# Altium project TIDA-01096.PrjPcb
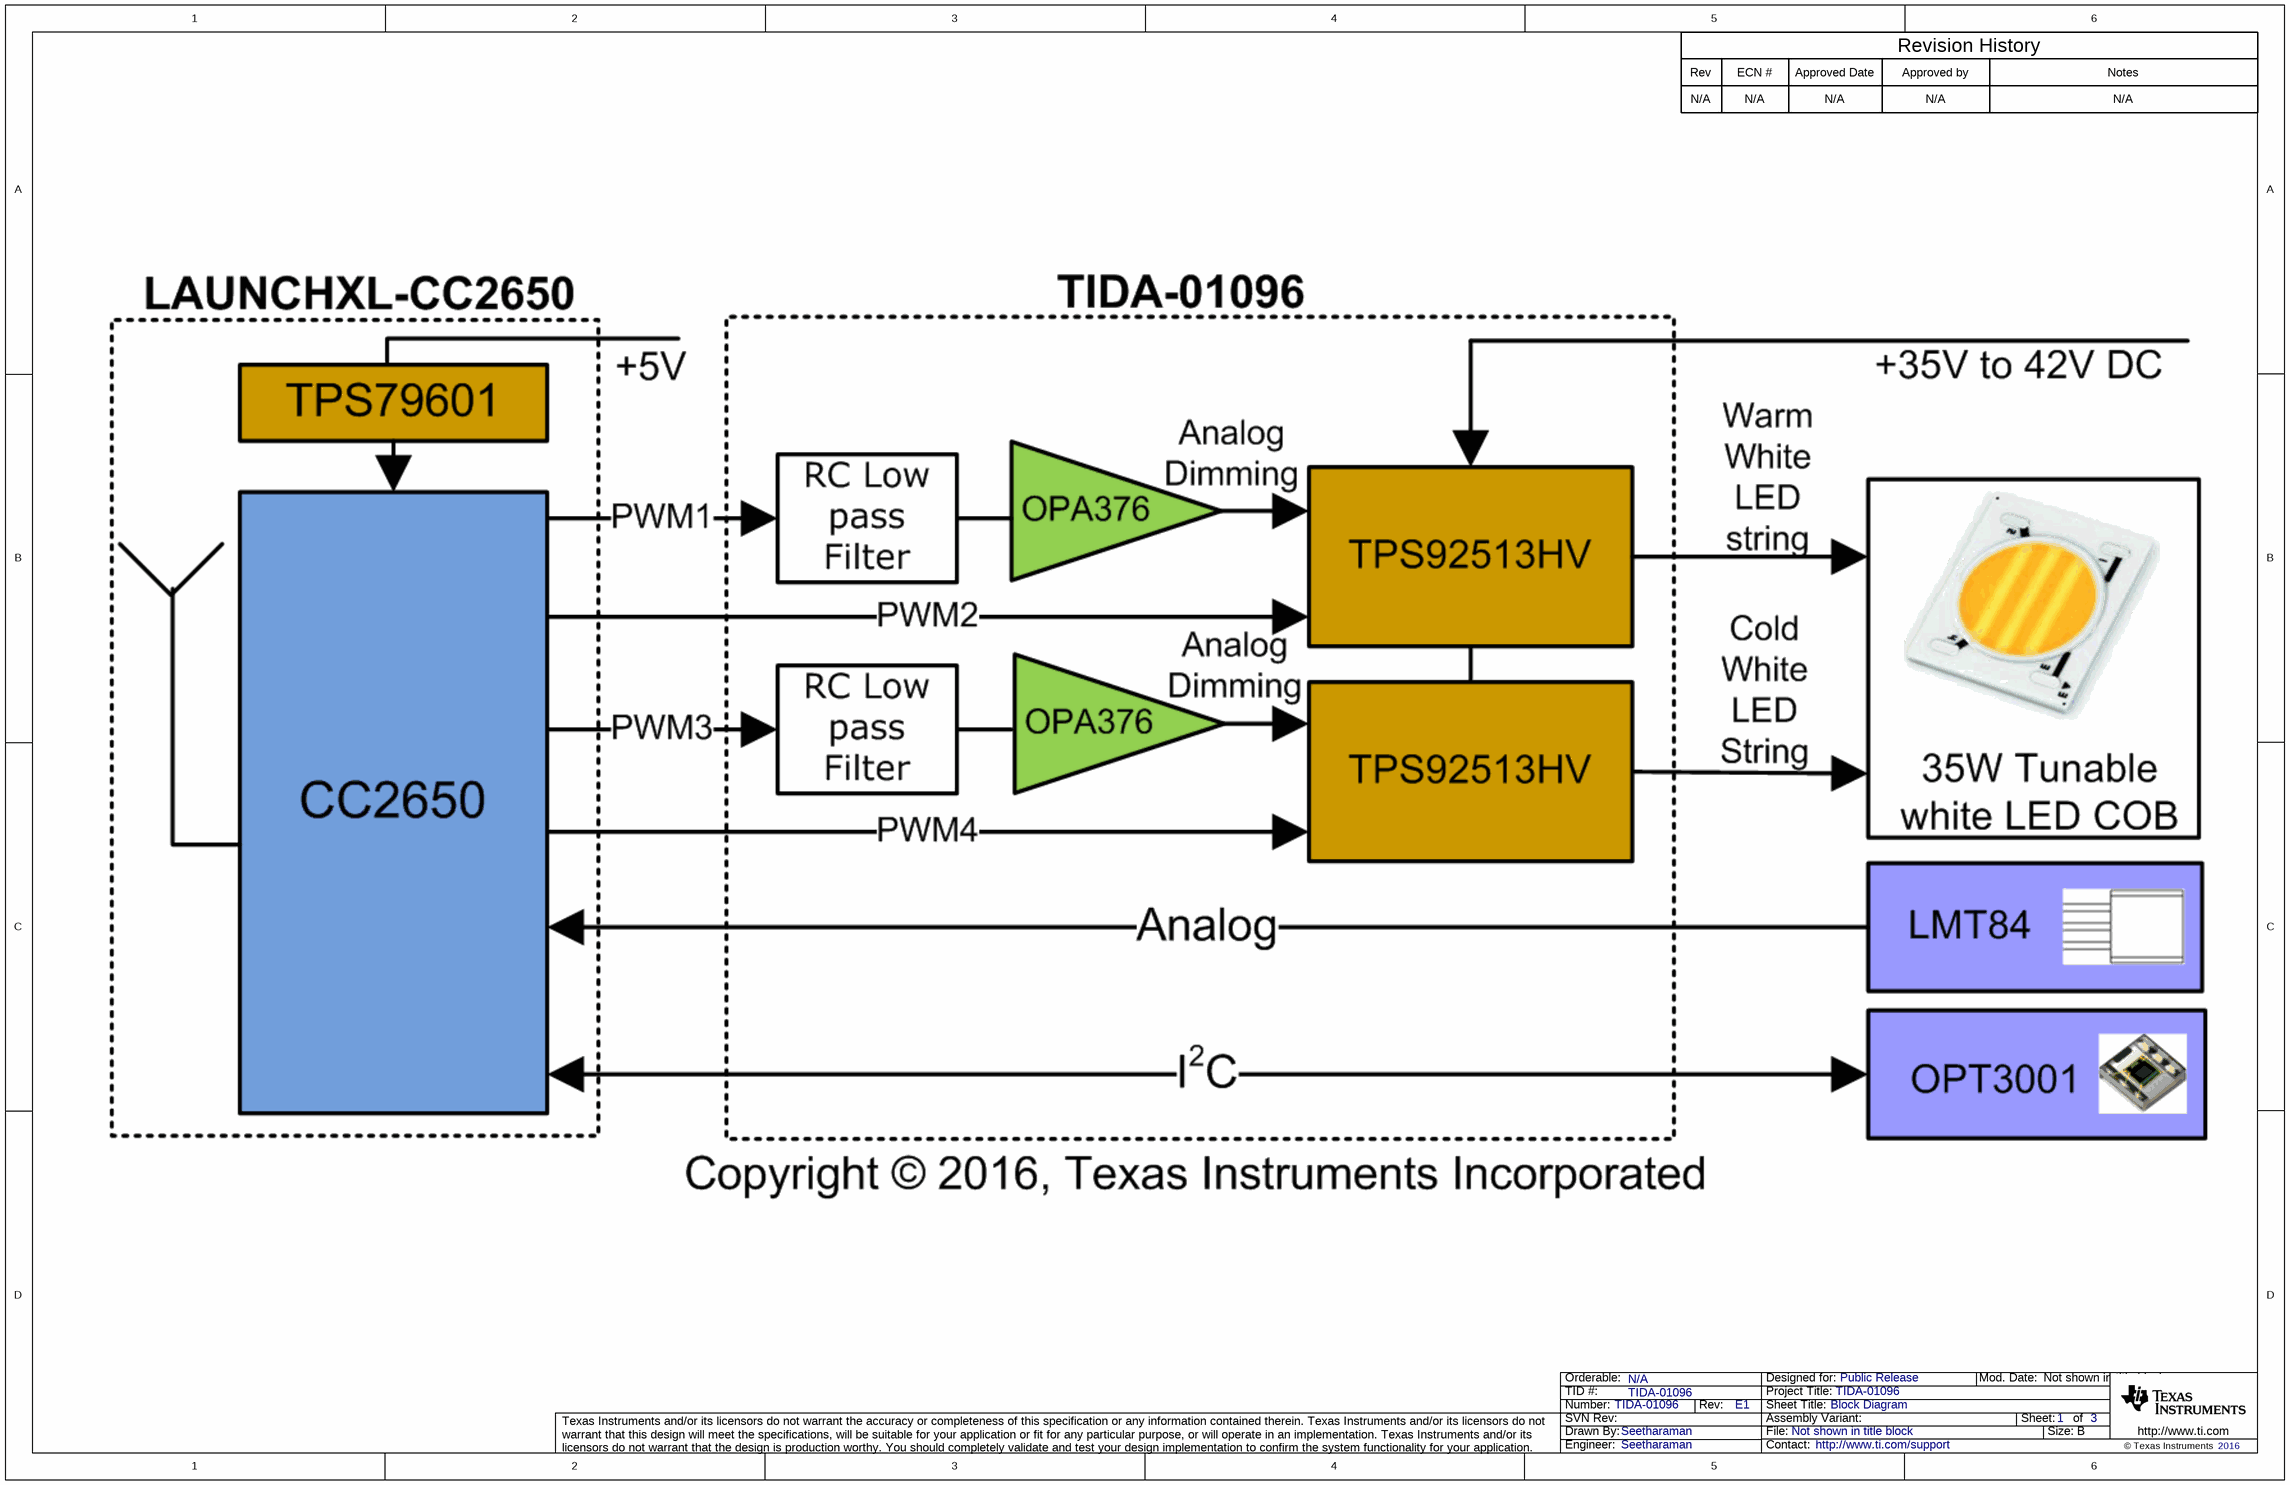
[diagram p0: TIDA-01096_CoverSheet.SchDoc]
CopyrightYear: 2016; EVM_Orderable: N/A; PCB_Layout: Avinash; PCB_Rev: E1; PRJ_Customer: Public Release; PRJ_Engineer: Seetharaman; PRJ_Number: TIDA-01096; PRJ_Title: TIDA-01096; SCH_Rev: E1; TechSupport: http://www.ti.com/support; TID: TIDA-01096
3 sheets, 118 parts. Net scope: global (net labels, ports and power ports of the same name join across sheets).
Board file: TIDA-01096.PcbDoc
Sheets:
  TIDA-01096_CoverSheet.SchDoc
  TIDA-01096_Sheet1.SchDoc
  TIDA-01096_Hardware.SchDoc

## Sheet TIDA-01096_CoverSheet.SchDoc: Block Diagram
size 431 x 279 mm; Date: Not shown in title block; ApprovedBy: Not shown in title block; CheckedBy: Not shown in title block; Author: Not shown in title block; CompanyName: Not shown in title block; DrawnBy: Seetharaman; Engineer: Not shown in title block; Organization: Not shown in title block; Address1: Not shown in title block; Address2: Not shown in title block; Address3: Not shown in title block; Address4: Not shown in title block; DocumentNumber: 1; Revision: Use project parameter SCH_Rev; SheetNumber: 1; SheetTotal: 3; PageSetup: Record=PageOptions¦CenterHorizontal=True¦CenterVertical=True¦PrintScale=1.00¦XCorrection=1.00¦YCorrection=1.00¦PrintKind=0¦BorderSize=5000000¦LeftOffset=0¦BottomOffset=0¦Orientation=2¦PaperLength=1000¦PaperWidth=1000¦Scale=100¦PaperSource=15¦PrintQuality=600¦MediaType=1¦DitherType=10¦PaperKind=Letter¦PrintScaleMode=1

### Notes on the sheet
- Rev
- N/A
- ECN #
- Approved Date
- Approved by
- Revision History
- Notes

## Sheet TIDA-01096_Sheet1.SchDoc: TIDA-01096
size 431 x 279 mm; Date: Not shown in title block; ApprovedBy: Not shown in title block; CheckedBy: Not shown in title block; Author: Not shown in title block; CompanyName: Not shown in title block; DrawnBy: Seetharaman; Engineer: Not shown in title block; Organization: Not shown in title block; Address1: Not shown in title block; Address2: Not shown in title block; Address3: Not shown in title block; Address4: Not shown in title block; DocumentNumber: 1; Revision: Use project parameter SCH_Rev; SheetNumber: 2; SheetTotal: 3; PageSetup: Record=PageOptions¦CenterHorizontal=True¦CenterVertical=True¦PrintScale=1.00¦XCorrection=1.00¦YCorrection=1.00¦PrintKind=0¦BorderSize=5000000¦LeftOffset=0¦BottomOffset=0¦Orientation=2¦PaperLength=1000¦PaperWidth=1000¦Scale=100¦PaperSource=15¦PrintQuality=600¦MediaType=1¦DitherType=10¦PaperKind=Letter¦PrintScaleMode=1
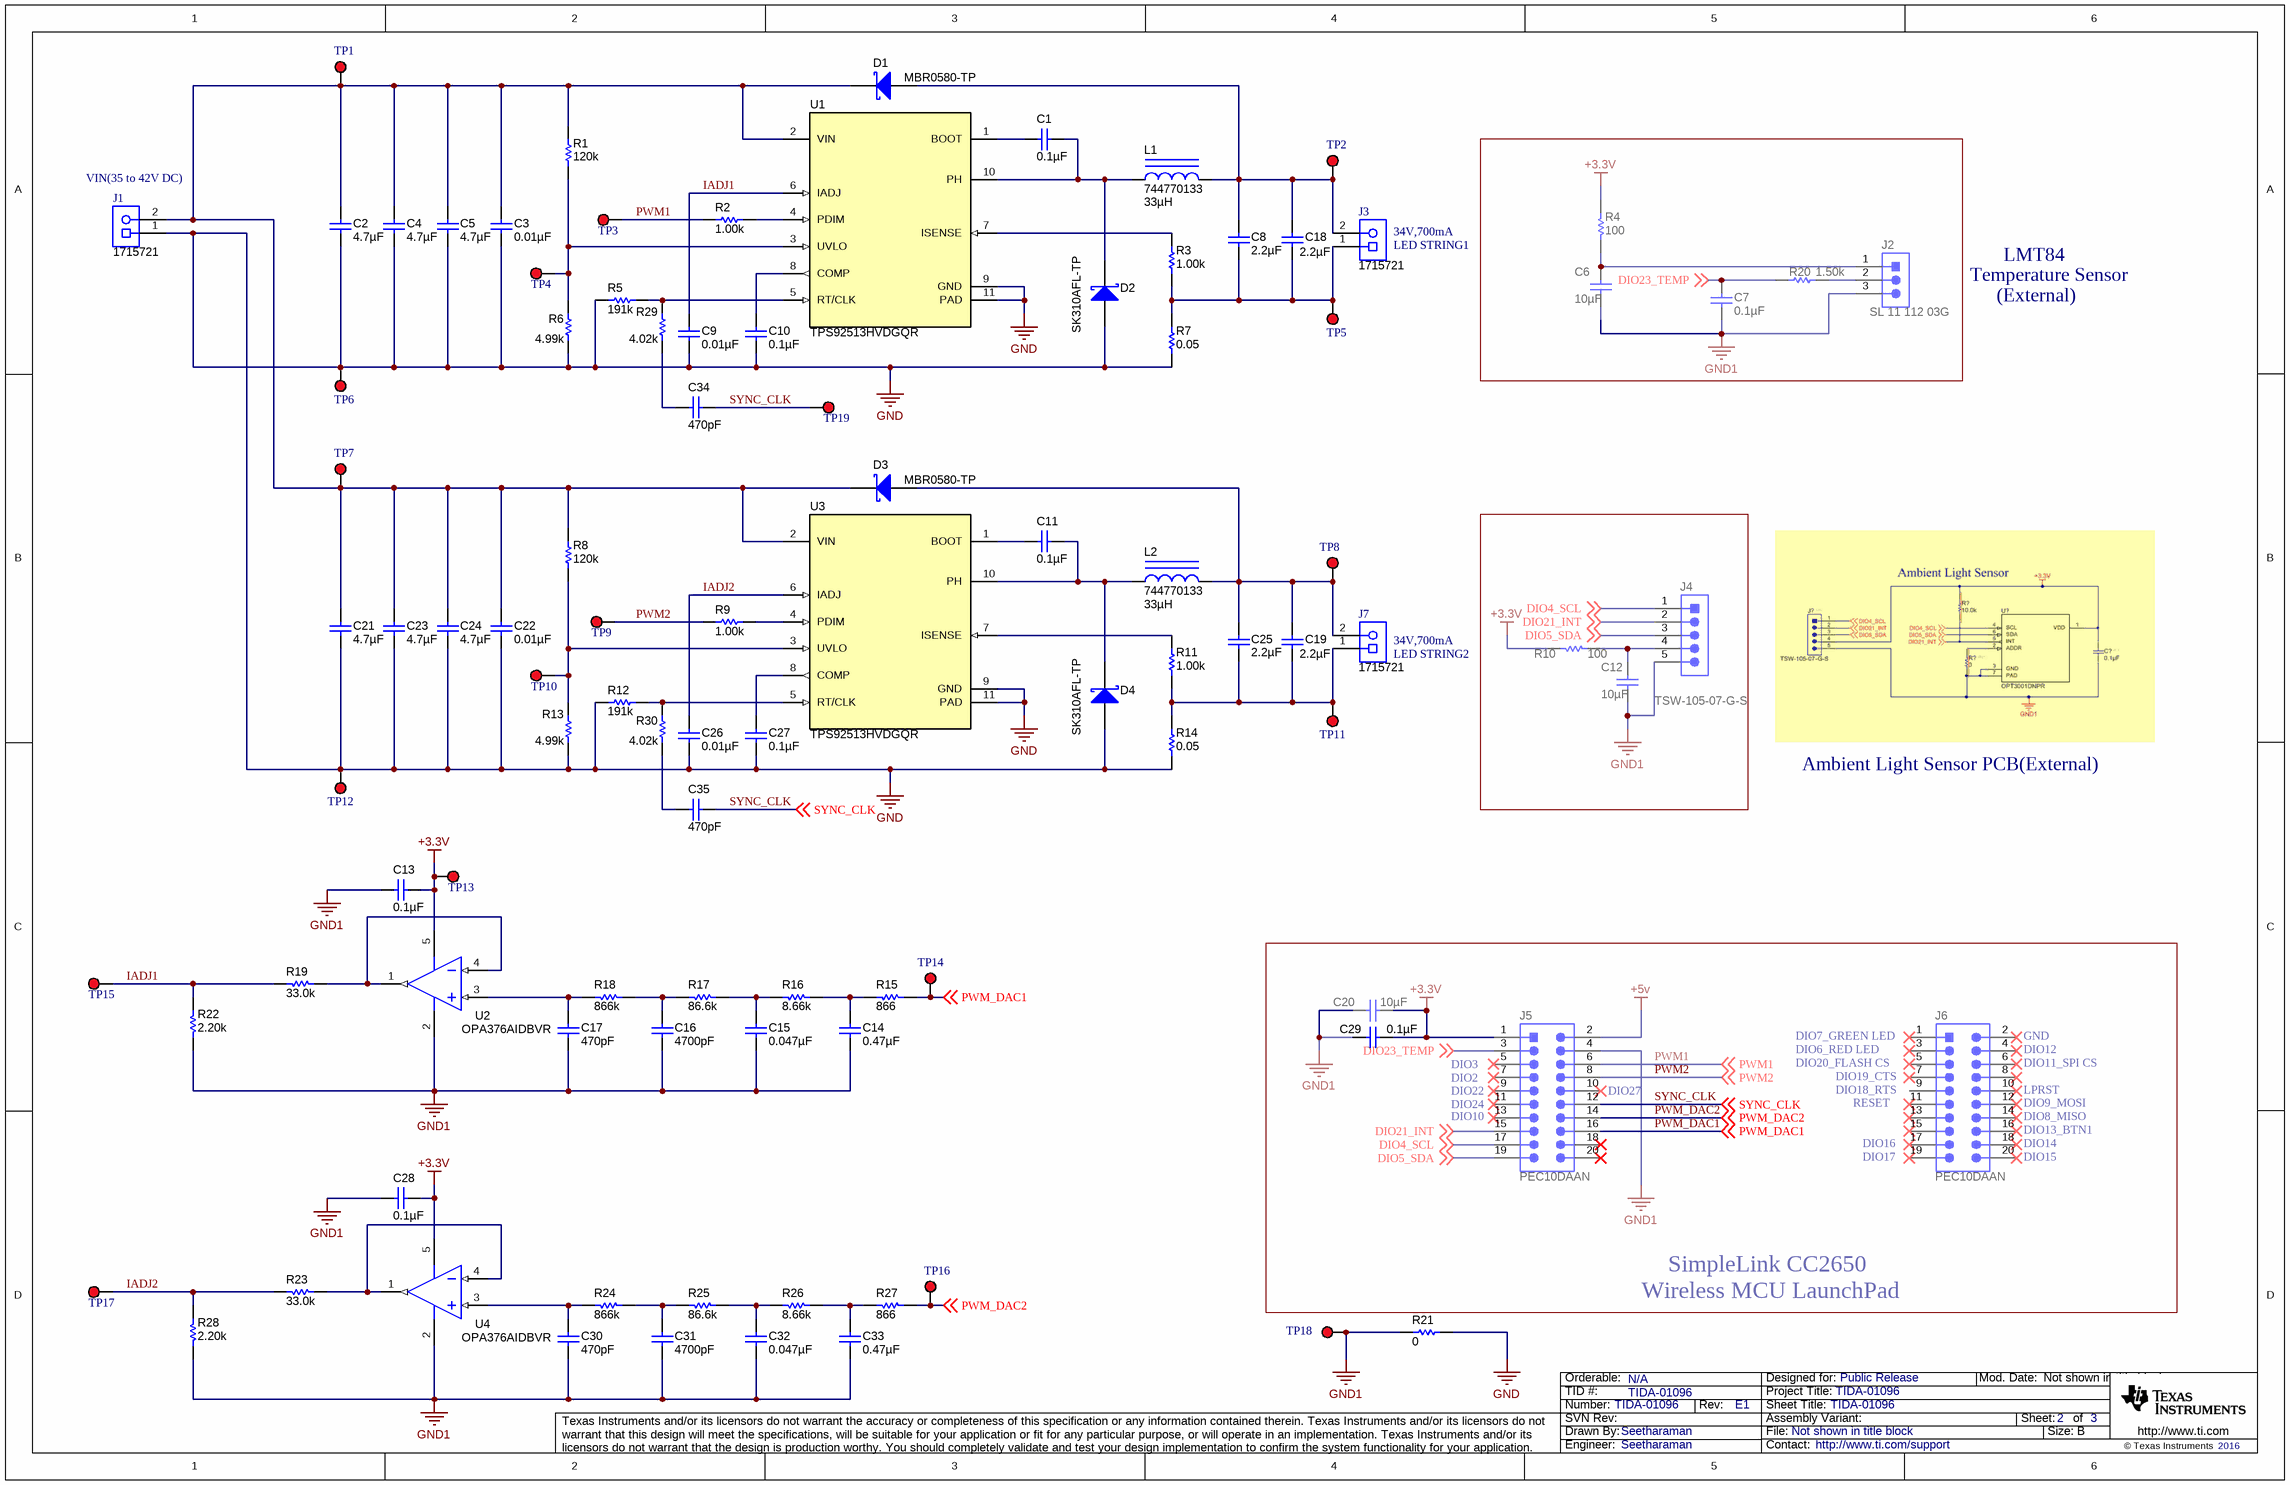
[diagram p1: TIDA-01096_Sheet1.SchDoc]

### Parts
C1  ValueDisplayed: 0.1µF  [0603]  (hidden comment: GRM188R71E104KA01D)
C2  ValueDisplayed: 4.7µF  [1210_220]  (hidden comment: GRJ32DC72A475KE11L)
C3  ValueDisplayed: 0.01µF  [0603]  (hidden comment: GCM188R72A103KA37D)
C4  ValueDisplayed: 4.7µF  [1210_220]  (hidden comment: GRJ32DC72A475KE11L)
C5  ValueDisplayed: 4.7µF  [1210_220]  (hidden comment: GRJ32DC72A475KE11L)
C6  ValueDisplayed: 10µF  [0603]  (hidden comment: GRT188C81A106ME13D)
C7  ValueDisplayed: 0.1µF  [0603]  (hidden comment: GCM188R71H104KA57D)
C8  ValueDisplayed: 2.2µF  [1210_270]  (hidden comment: GRM32ER72A225KA35L)
C9  ValueDisplayed: 0.01µF  [0603]  (hidden comment: GRM188R71E103KA01D)
C10  ValueDisplayed: 0.1µF  [0603]  (hidden comment: GCM188R71H104KA57D)
C11  ValueDisplayed: 0.1µF  [0603]  (hidden comment: GRM188R71E104KA01D)
C12  ValueDisplayed: 10µF  [0603]  (hidden comment: GRT188C81A106ME13D)
C13  ValueDisplayed: 0.1µF  [0603]  (hidden comment: GCM188R71H104KA57D)
C14  ValueDisplayed: 0.47µF  [0603]  (hidden comment: GRM188R71A474KA61D)
C15  ValueDisplayed: 0.047µF  [0402]  (hidden comment: GRM155R71A473KA01D)
C16  ValueDisplayed: 4700pF  [0603]  (hidden comment: GCM188R72A103KA37D)
C17  ValueDisplayed: 470pF  [0603]  (hidden comment: C0603X471K5RACTU)
C18  ValueDisplayed: 2.2µF  [1210_270]  (hidden comment: GRM32ER72A225KA35L)
C19  ValueDisplayed: 2.2µF  [1210_270]  (hidden comment: GRM32ER72A225KA35L)
C20  ValueDisplayed: 10µF  [0603]  (hidden comment: GRT188C81A106ME13D)
C21  ValueDisplayed: 4.7µF  [1210_220]  (hidden comment: GRJ32DC72A475KE11L)
C22  ValueDisplayed: 0.01µF  [0603]  (hidden comment: GCM188R72A103KA37D)
C23  ValueDisplayed: 4.7µF  [1210_220]  (hidden comment: GRJ32DC72A475KE11L)
C24  ValueDisplayed: 4.7µF  [1210_220]  (hidden comment: GRJ32DC72A475KE11L)
C25  ValueDisplayed: 2.2µF  [1210_270]  (hidden comment: GRM32ER72A225KA35L)
C26  ValueDisplayed: 0.01µF  [0603]  (hidden comment: GRM188R71E103KA01D)
C27  ValueDisplayed: 0.1µF  [0603]  (hidden comment: GCM188R71H104KA57D)
C28  ValueDisplayed: 0.1µF  [0603]  (hidden comment: GCM188R71H104KA57D)
C29  ValueDisplayed: 0.1µF  [0603]  (hidden comment: GRM188R71E104KA01D)
C30  ValueDisplayed: 470pF  [0603]  (hidden comment: C0603X471K5RACTU)
C31  ValueDisplayed: 4700pF  [0603]  (hidden comment: GCM188R72A103KA37D)
C32  ValueDisplayed: 0.047µF  [0402]  (hidden comment: GRM155R71A473KA01D)
C33  ValueDisplayed: 0.47µF  [0603]  (hidden comment: GRM188R71A474KA61D)
C34  ValueDisplayed: 470pF  [0603]  (hidden comment: C0603X471K5RACTU)
C35  ValueDisplayed: 470pF  [0603]  (hidden comment: C0603X471K5RACTU)
D1  MBR0580-TP  [SOD-123]
D2  SK310AFL-TP  [SMA]
D3  MBR0580-TP  [SOD-123]
D4  SK310AFL-TP  [SMA]
J1  1715721  [PhoenixContact_1715721]
J2  SL 11 112 03G  [Fischer_SL-11-112-03G]
J3  1715721  [PhoenixContact_1715721]
J4  TSW-105-07-G-S  [TSW-105-07-G-S]
J5  PEC10DAAN  [SULLINS_PEC10DAAN]
J6  PEC10DAAN  [SULLINS_PEC10DAAN]
J7  1715721  [PhoenixContact_1715721]
L1  744770133  ValueDisplayed: 33µH  [WE-PD-XL]
L2  744770133  ValueDisplayed: 33µH  [WE-PD-XL]
R1  ValueDisplayed: 120k  [0603]  (hidden comment: CRCW0603120KFKEA)
R2  ValueDisplayed: 1.00k  [0603]  (hidden comment: CRCW06031K00FKEA)
R3  ValueDisplayed: 1.00k  [0603]  (hidden comment: CRCW06031K00FKEA)
R4  ValueDisplayed: 100  [0603]  (hidden comment: RC0603FR-07100RL)
R5  ValueDisplayed: 191k  [0603]  (hidden comment: CRCW0603191KFKEA)
R6  ValueDisplayed: 4.99k  [0603]  (hidden comment: CRCW06034K99FKEA)
R7  ValueDisplayed: 0.05  [2512]  (hidden comment: CSRN2512FK50L0CT-ND)
R8  ValueDisplayed: 120k  [0603]  (hidden comment: CRCW0603120KFKEA)
R9  ValueDisplayed: 1.00k  [0603]  (hidden comment: CRCW06031K00FKEA)
R10  ValueDisplayed: 100  [0603]  (hidden comment: RC0603FR-07100RL)
R11  ValueDisplayed: 1.00k  [0603]  (hidden comment: CRCW06031K00FKEA)
R12  ValueDisplayed: 191k  [0603]  (hidden comment: CRCW0603191KFKEA)
R13  ValueDisplayed: 4.99k  [0603]  (hidden comment: CRCW06034K99FKEA)
R14  ValueDisplayed: 0.05  [2512]  (hidden comment: CSRN2512FK50L0CT-ND)
R15  ValueDisplayed: 866  [0603]  (hidden comment: CRCW0603866RFKEA)
R16  ValueDisplayed: 8.66k  [0603]  (hidden comment: CRCW06038K66FKEA)
R17  ValueDisplayed: 86.6k  [0603]  (hidden comment: CRCW060386K6FKEA)
R18  ValueDisplayed: 866k  [0603]  (hidden comment: CRCW0603866KFKEA)
R19  ValueDisplayed: 33.0k  [0603]  (hidden comment: CRCW060333K0FKEA)
R20  ValueDisplayed: 1.50k  [0603]  (hidden comment: RC0603FR-071K5L)
R21  ValueDisplayed: 0  [1206]  (hidden comment: CRCW12060000Z0EA)
R22  ValueDisplayed: 2.20k  [0603]  (hidden comment: CRCW06032K20FKEA)
R23  ValueDisplayed: 33.0k  [0603]  (hidden comment: CRCW060333K0FKEA)
R24  ValueDisplayed: 866k  [0603]  (hidden comment: CRCW0603866KFKEA)
R25  ValueDisplayed: 86.6k  [0603]  (hidden comment: CRCW060386K6FKEA)
R26  ValueDisplayed: 8.66k  [0603]  (hidden comment: CRCW06038K66FKEA)
R27  ValueDisplayed: 866  [0603]  (hidden comment: CRCW0603866RFKEA)
R28  ValueDisplayed: 2.20k  [0603]  (hidden comment: CRCW06032K20FKEA)
R29  ValueDisplayed: 4.02k  [0603]  (hidden comment: CRCW06034K02FKEA)
R30  ValueDisplayed: 4.02k  [0603]  (hidden comment: CRCW06034K02FKEA)
TP1  5000  [Keystone5000]  (value not drawn)
TP2  5000  [Keystone5000]  (value not drawn)
TP3  5000  [Keystone5000]  (value not drawn)
TP4  5000  [Keystone5000]  (value not drawn)
TP5  5000  [Keystone5000]  (value not drawn)
TP6  5000  [Keystone5000]  (value not drawn)
TP7  5000  [Keystone5000]  (value not drawn)
TP8  5000  [Keystone5000]  (value not drawn)
TP9  5000  [Keystone5000]  (value not drawn)
TP10  5000  [Keystone5000]  (value not drawn)
TP11  5000  [Keystone5000]  (value not drawn)
TP12  5000  [Keystone5000]  (value not drawn)
TP13  5000  [Keystone5000]  (value not drawn)
TP14  5000  [Keystone5000]  (value not drawn)
TP15  5000  [Keystone5000]  (value not drawn)
TP16  5000  [Keystone5000]  (value not drawn)
TP17  5000  [Keystone5000]  (value not drawn)
TP18  5000  [Keystone5000]  (value not drawn)
TP19  5000  [Keystone5000]  (value not drawn)
U1  TPS92513HVDGQR  [DGQ0010D_N]
U2  OPA376AIDBVR  [DBV0005A_N]
U3  TPS92513HVDGQR  [DGQ0010D_N]
U4  OPA376AIDBVR  [DBV0005A_N]

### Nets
+3.3V: C13.1 C20.1 C28.1 C29.1 J5.1 R4.2 R10.1 TP13.1 U2.5(V+) U4.5(V+)
+5v: J5.2
GND: C2.2 C3.2 C4.2 C5.2 C9.2 C10.2 C21.2 C22.2 C23.2 C24.2 C26.2 C27.2 D2.2(A) D4.2(A) J1.1 R5.1 R6.1 R7.1 R12.1 R13.1 R14.1 R21.2 TP6.1 TP12.1 U1.9(GND) U1.11(PAD) U3.9(GND) U3.11(PAD)
GND1: C6.2 C7.2 C12.2 C13.2 C14.2 C15.2 C16.2 C17.2 C20.2 C28.2 C29.2 C30.2 C31.2 C32.2 C33.2 J2.3 J4.5 J5.4 R21.1 R22.2 R28.2 TP18.1 U2.2(V-) U4.2(V-)
DIO4_SCL: J4.1 J5.17 ; off-sheet DIO4_SCL
DIO5_SDA: J4.3 J5.19 ; off-sheet DIO5_SDA
DIO21_INT: J4.2 J5.15 ; off-sheet DIO21_INT
DIO23_TEMP: C7.1 J5.3 R20.1 ; off-sheet DIO23_TEMP
IADJ1: C9.1 R19.2 R22.1 TP15.1 U1.6(IADJ)
IADJ2: C26.1 R23.2 R28.1 TP17.1 U3.6(IADJ)
PWM1: J5.6 R2.1 TP3.1 ; off-sheet PWM1
PWM2: J5.8 R9.1 TP9.1 ; off-sheet PWM2
PWM_DAC1: J5.16 R15.1 TP14.1 ; off-sheet PWM_DAC1
PWM_DAC2: J5.14 R27.1 TP16.1 ; off-sheet PWM_DAC2
SYNC_CLK: C34.2 C35.2 J5.12 TP19.1 ; off-sheet SYNC_CLK
NetC1_1: C1.1 U1.1(BOOT)
NetC1_2: C1.2 D2.1(K) L1.1 U1.10(PH)
NetC2_1: C2.1 C3.1 C4.1 C5.1 C21.1 C22.1 C23.1 C24.1 D1.1(K) D3.1(K) J1.2 R1.2 R8.2 TP1.1 TP7.1 U1.2(VIN) U3.2(VIN)
NetC6_1: C6.1 J2.1 R4.1
NetC8_1: C8.1 C18.1 D1.2(A) J3.2 L1.2 TP2.1
NetC8_2: C8.2 C18.2 J3.1 R3.1 R7.2 TP5.1
NetC10_1: C10.1 U1.8(COMP)
NetC11_1: C11.1 U3.1(BOOT)
NetC11_2: C11.2 D4.1(K) L2.1 U3.10(PH)
NetC12_1: C12.1 J4.4 R10.2
NetC14_1: C14.1 R15.2 R16.1
NetC15_1: C15.1 R16.2 R17.1
NetC16_1: C16.1 R17.2 R18.1
NetC17_1: C17.1 R18.2 U2.3(IN+)
NetC19_1: C19.1 C25.1 D3.2(A) J7.2 L2.2 TP8.1
NetC19_2: C19.2 C25.2 J7.1 R11.1 R14.2 TP11.1
NetC27_1: C27.1 U3.8(COMP)
NetC30_1: C30.1 R24.2 U4.3(IN+)
NetC31_1: C31.1 R24.1 R25.2
NetC32_1: C32.1 R25.1 R26.2
NetC33_1: C33.1 R26.1 R27.2
NetC34_1: C34.1 R29.1
NetC35_1: C35.1 R30.1
NetJ2_2: J2.2 R20.2
NetR1_1: R1.1 R6.2 TP4.1 U1.3(UVLO)
NetR2_2: R2.2 U1.4(PDIM)
NetR3_2: R3.2 U1.7(ISENSE)
NetR5_2: R5.2 R29.2 U1.5(RT/CLK)
NetR8_1: R8.1 R13.2 TP10.1 U3.3(UVLO)
NetR9_2: R9.2 U3.4(PDIM)
NetR11_2: R11.2 U3.7(ISENSE)
NetR12_2: R12.2 R30.2 U3.5(RT/CLK)
NetR19_1: R19.1 U2.1(OUT) U2.4(IN-)
NetR23_1: R23.1 U4.1(OUT) U4.4(IN-)

Not connected (* = marked no-connect by the designer): J5 5* 7* 9* 10* 11* 13* 18* 20*; J6 1* 2* 3* 4* 5* 6* 7* 8* 9 10* 11* 12* 13* 14* 15* 16* 17* 18* 19* 20*

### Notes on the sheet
- (near J1) VIN(35 to 42V DC)
- (near J3) 34V,700mA
- (near J3) LED STRING1
- Temperature Sensor
- (External)
- LMT84
- (near J7) 34V,700mA
- (near J7) LED STRING2
- Ambient Light Sensor PCB(External)
- (near J5) DIO3
- (near J5) DIO2
- (near J5) DIO22
- (near J5) DIO27
- DIO7_GREEN LED
- DIO6_RED LED
- DIO20_FLASH CS
- (near J6) DIO19_CTS
- (near J6) DIO18_RTS
- (near J6) RESET
- (near J6) DIO11_SPI CS
- (near J6) LPRST
- (near J6) DIO9_MOSI
- (near J6) DIO12
- (near J6) GND
- (near J5) DIO24
- (near J5) DIO10
- (near J6) DIO16
- (near J6) DIO17
- (near J6) DIO8_MISO
- (near J6) DIO13_BTN1
- (near J6) DIO14
- (near J6) DIO15
- Wireless MCU LaunchPad
- SimpleLink CC2650

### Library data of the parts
C1 C11 = GRM188R71E104KA01D: CAP, CERM, 0.1 µF, 25 V, +/- 10%, X7R, 0603; Manufacturer: MuRata; Polarized: N; CompType: Capacitor; Value: 0.1uF; U/M: EA; Cap_F: 0.0000001; Tolerance_%: 10; Value1: Unknown; VDC_V: 25; Value2: 25V; TaMin_C: -55; TaMax_C: 125; SizeArea_mm2: 1.28; SizeAreaWB_mm2: 4.68; SizeX_mm: 1.6; SizeY_mm: 0.8; SizeZ_mm: 1; AEC Category: Q200
C2 C4 C5 C21 C23 C24 = C3225X7S2A475K200AB: 4.7µF ±10% 100V X7S Ceramic Capacitor -55°C ~ 125°C Surface Mount, MLCC 1210 (3225 Metric) 0.126" L x 0.098" W (3.20mm x 2.50mm); Manufacturer: Murata Electronics North America; Polarized: N; Value: 4.7uF; U/M: EA; Cap_F: 0.0000047; Tolerance_%: 10; ESR_ohm: 0.004236; Value1: 0.004236 ohm; VDC_V: 100; IRMS_A: 3.57337; TaMin_C: -55; TaMax_C: 125; SizeArea_mm2: 8; SizeAreaWB_mm2: 14.7; SizeX_mm: 3.2; SizeY_mm: 2.5; SizeZ_mm: 2.2; AEC Category: Q200
C3 C22 = 06031C103KAT2A: 10000pF ±10% 100V X7R Ceramic Capacitor -55°C ~ 125°C Surface Mount, MLCC 0603 (1608 Metric) 0.063" L x 0.031" W (1.60mm x 0.80mm); Manufacturer: Murata Electronics North America; Polarized: N; Value: 0.01uF; U/M: EA; Cap_F: 0.00000001; Tolerance_%: 10; ESR_ohm: 0.098; Value1: 0.098 ohm; VDC_V: 100; TaMin_C: -55; TaMax_C: 125; SizeArea_mm2: 1.28; SizeAreaWB_mm2: 4.68; SizeX_mm: 1.6; SizeY_mm: 0.8; SizeZ_mm: 1; AEC Category: Q200
C6 C12 C20 = GRT188C81A106ME13D: CAP, CERM, 10 µF, 10 V, +/- 20%, X6S, AEC-Q200 Grade 2, 0603; Manufacturer: MuRata; Polarized: N; CompType: Capacitor; Value: 10uF; U/M: EA; Cap_F: 0.00001; Tolerance_%: 20; Value1: Unknown; VDC_V: 10; Value2: 10V; TaMin_C: -55; TaMax_C: 105; AEC Category: Q200; AEC Qualified: Y; AEC Grade: 2
C7 C13 C28 = GCM188R71H104KA57D: CAP, CERM, 0.1 µF, 50 V, +/- 10%, X7R, 0603; Manufacturer: MuRata; Polarized: N; CompType: Capacitor; Value: 0.1uF; U/M: EA; Cap_F: 0.0000001; Tolerance_%: 10; ESR_ohm: 0.02; Value1: 0.02 ohm; VDC_V: 50; Value2: 50V; IRMS_A: 1.84; TaMin_C: -55; TaMax_C: 125; AEC Category: Q200; SizeArea_mm2: 1.28; SizeAreaWB_mm2: 4.68; SizeX_mm: 1.6; SizeY_mm: 0.8; SizeZ_mm: 1
C8 C18 C19 = GRM32ER72A225KA35L: CAP, CERM, 2.2 µF, 100 V, +/- 10%, X7R, 1210; Manufacturer: MuRata; Polarized: N; CompType: Capacitor; Value: 2.2uF; U/M: EA; Cap_F: 0.0000022; Tolerance_%: 10; ESR_ohm: 0.007; Value1: 0.007 ohm; VDC_V: 100; Value2: 100V; IRMS_A: 4.4; TaMin_C: -55; TaMax_C: 125; Cap_Case: 1210; AEC Category: Q200
C9 C26 = GRM188R71E103KA01D: CAP, CERM, 0.01 µF, 25 V, +/- 10%, X7R, 0603; Manufacturer: MuRata; Polarized: N; CompType: Capacitor; Value: 0.01uF; U/M: EA; Cap_F: 0.00000001; Tolerance_%: 10; Value1: Unknown; VDC_V: 25; Value2: 25V; TaMin_C: -55; TaMax_C: 125; SizeArea_mm2: 1.28; SizeAreaWB_mm2: 4.68; SizeX_mm: 1.6; SizeY_mm: 0.8; SizeZ_mm: 1; AEC Category: Q200
C10 C27 = GCM188R71H104KA57D: CAP, CERM, 0.1 µF, 50 V, +/- 10%, X7R, 0603; Manufacturer: MuRata; Polarized: N; CompType: Capacitor; Value: 0.1uF; U/M: EA; Cap_F: 0.0000001; Tolerance_%: 10; ESR_ohm: 0.02; Value1: 0.02 ohm; VDC_V: 50; Value2: 50V; IRMS_A: 1.84; TaMin_C: -55; TaMax_C: 125; SizeArea_mm2: 1.28; SizeAreaWB_mm2: 4.68; SizeX_mm: 1.6; SizeY_mm: 0.8; SizeZ_mm: 1; AEC Category: Q200
C14 C33 = GRM188R71A474KA61D: CAP, CERM, 0.47 µF, 10 V, +/- 10%, X7R, 0603; Manufacturer: MuRata; Polarized: N; CompType: Capacitor; Value: 0.47uF; U/M: EA; Cap_F: 0.00000047; Tolerance_%: 10; Value1: Unknown; Value2: 10V; TaMin_C: -55; TaMax_C: 125; AEC Category: Q200; SizeArea_mm2: 1.28; SizeAreaWB_mm2: 4.68; SizeX_mm: 1.6; SizeY_mm: 0.8; SizeZ_mm: 1
C15 C32 = GRM155R71A473KA01D: CAP, CERM, 0.047 µF, 10 V, +/- 10%, X7R, 0402; Manufacturer: MuRata; Polarized: N; CompType: Capacitor; Value: 0.047uF; U/M: EA; Cap_F: 0.000000047; Tolerance_%: 10; Value1: Unknown; Value2: 10V; TaMin_C: -55; TaMax_C: 125; AEC Category: Q200; SizeArea_mm2: 0.5; SizeAreaWB_mm2: 3; SizeX_mm: 1; SizeZ_mm: 0.6
C16 C31 = GCM188R71H472KA37D: 10000pF ±10% 100V X7R Ceramic Capacitor -55°C ~ 125°C Surface Mount, MLCC 0603 (1608 Metric) 0.063" L x 0.031" W (1.60mm x 0.80mm); Manufacturer: Maruta; Polarized: N; Value: 4700pF; U/M: EA; Cap_F: 0.0000000047; Tolerance_%: 10; Value1: Unknown; VDC_V: 50; Value2: 50V; TaMin_C: -55; TaMax_C: 125; AEC Category: Q200; AEC Qualified: Y; AEC Grade: 1
C17 C30 = C0603X471K5RACTU: CAP, CERM, 470 pF, 50 V, +/- 10%, X7R, 0603; Manufacturer: Kemet; Polarized: N; CompType: Capacitor; Value: 470pF; U/M: EA; Cap_F: 0.00000000047; Tolerance_%: 10; Value1: Unknown; VDC_V: 50; Value2: 50V; TaMin_C: -55; TaMax_C: 125; AEC Category: Q200; SizeArea_mm2: 1.28; SizeAreaWB_mm2: 4.68; SizeX_mm: 1.6; SizeY_mm: 0.8; SizeZ_mm: 1
C25 = GRM32ER72A225KA35L: CAP, CERM, 2.2 µF, 100 V, +/- 10%, X7R, 1210; Manufacturer: MuRata; Polarized: N; CompType: Capacitor; Value: 2.2uF; U/M: EA; Cap_F: 0.0000022; Tolerance_%: 10; ESR_ohm: 0.007; Value1: 0.007 ohm; VDC_V: 100; Value2: 100V; IRMS_A: 4.4; TaMin_C: -55; TaMax_C: 125; Cap_Case: 1210; SizeArea_mm2: 8; SizeAreaWB_mm2: 14.7; SizeX_mm: 3.2; SizeY_mm: 2.5; SizeZ_mm: 2.7; AEC Category: Q200
C29 = GRM188R71E104KA01D: CAP, CERM, 0.1 µF, 25 V, +/- 10%, X7R, 0603; Manufacturer: MuRata; Polarized: N; CompType: Capacitor; Value: 0.1uF; U/M: EA; Cap_F: 0.0000001; Tolerance_%: 10; Value1: Unknown; VDC_V: 25; Value2: 25V; TaMin_C: -55; TaMax_C: 125; AEC Category: Q200
C34 C35 = C0603X471K5RACTU: CAP, CERM, 470 pF, 50 V, +/- 10%, X7R, 0603; Manufacturer: Kemet; Polarized: N; CompType: Capacitor; Value: 470pF; U/M: EA; Cap_F: 0.00000000047; Tolerance_%: 10; Value1: Unknown; VDC_V: 50; Value2: 50V; TaMin_C: -55; TaMax_C: 125; SizeArea_mm2: 1.28; SizeAreaWB_mm2: 4.68; SizeX_mm: 1.6; SizeY_mm: 0.8; SizeZ_mm: 1; AEC Category: Q200
D1 D3 = MBR0580-TP: Diode, Schottky, 80 V, 0.5 A, SOD-123; Manufacturer: Micro Commercial Components; U/M: EA; Vf_V: 0.8; Value: 80V; Value1: 0.5A; Value2: 0.8V; Io_A: 0.5; Vr_V: 80; TJmax_C: 150; SizeAreaWB_mm2: 13.095; SizeArea_mm2: 6.545; SizeX_mm: 3.85; SizeY_mm: 1.7; SizeZ_mm: 1.35; AEC Category: Q101
D2 D4 = CDBA280-G: DIODE SCHOTTKY 100V 3A DO221AC; Manufacturer: Micro Commercial Co; U/M: EA; Vf_V: 0.85; Value: 80V; Value1: 2A; Value2: 0.85V; Io_A: 2; Vr_V: 80; TJmax_C: 125; SizeAreaWB_mm2: 37.3428; SizeArea_mm2: 16.3228; SizeX_mm: 5.59; SizeY_mm: 2.92; SizeZ_mm: 2.87; AEC Category: Q101
J1 J3 J7 = 1715721: Terminal Block, 5.08 mm, 2x1, TH; Manufacturer: Phoenix Contact; SymbolCreator: a0412235; Pitch_mm: 5.08; Gender: Female; Row_Count: 1; ContactFinish: Tin; Current_A: 17.5; Voltage_V: 400; Cert_CSA: Y; Cert_CULUS: N
J2 = SL 11 112 03G: Header, 2.54mm, 3x1, Gold, TH; Manufacturer: Fischer Elektronik; SymbolCreator: a0799628
J4 = TSW-105-07-G-S: Header, 100mil, 5x1, Gold, TH; Manufacturer: Samtec; SymbolCreator: a0412235; U/M: EA
J5 J6 = PEC10DAAN: Header, 100mil, 10x2, TH; Manufacturer: Sullins Connector Solutions; SymbolCreator: a0412235; U/M: EA
L1 L2 = 744770133: Inductor, Shielded Drum Core, Ferrite, 33uH, 3.2A, 0.047 ohm, SMD; Manufacturer: Wurth Elektronik eiSos; Ind_H: 33.0E-6; Imax_A: 3.2; Irms: 3.2A @ 40C rise; Isat: 3.6A @ 10% inductance drop; DCR_ohm: 0.047; U/M: EA
R1 R8 = RC0603FR-07120KL: RES SMD 120K OHM 1% 1/10W 0603; Manufacturer: Vishay Dale; CompType: Resistor; Res_ohm: 120000; Tolerance_%: 1; Power_W: 0.1; Value2: 0.1W; VDC_V: 150; TempCo: 200 ppm/C; SizeArea_mm2: 1.28; SizeX_mm: 1.6; SizeY_mm: 0.8; U/M: EA; AEC Category: Q200
R2 R3 R9 R11 = CRCW06031K00FKEA: RES, 1.00 k, 1%, 0.1 W, 0603; Manufacturer: Vishay-Dale; CompType: Resistor; Value: 1.00k; Res_ohm: 1000; Value_Code: 1k00; Tolerance_%: 1; Power_W: 0.1; Value2: 0.1W; VDC_V: 75; TempCo: 100 ppm/C; SizeArea_mm2: 1.28; SizeX_mm: 1.6; SizeY_mm: 0.8; EIA_Code: E96; U/M: EA; AEC Category: Q200
R4 R10 = RC0603FR-07100RL: RES, 100, 1%, 0.1 W, 0603; Manufacturer: Yageo America; CompType: Resistor; Value: 100; Value_Code: 100R; Tolerance_%: 1; Power_W: 0.1; Value2: 0.1W; VDC_V: 150; TempCo: 200 ppm/C; EIA_Code: E96; U/M: EA; AEC Category: Q200
R5 R12 = CRCW0603191KFKEA: RES, 191 k, 1%, 0.1 W, 0603; Manufacturer: Vishay-Dale; CompType: Resistor; Value: 191k; Res_ohm: 191000; Tolerance_%: 1; Power_W: 0.1; Value2: 0.1W; VDC_V: 75; TempCo: 100 ppm/C; SizeArea_mm2: 1.28; SizeX_mm: 1.6; SizeY_mm: 0.8; EIA_Code: E96; U/M: EA; AEC Category: Q200
R6 R13 = CRCW06034K99FKEA: RES, 4.99 k, 1%, 0.1 W, 0603; Manufacturer: Vishay-Dale; CompType: Resistor; Value: 4.99k; Res_ohm: 4990; Value_Code: 4k99; Tolerance_%: 1; Power_W: 0.1; Value2: 0.1W; VDC_V: 75; TempCo: 100 ppm/C; SizeArea_mm2: 1.28; SizeX_mm: 1.6; SizeY_mm: 0.8; EIA_Code: E96; U/M: EA; AEC Category: Q200
R7 R14 = CSRN2512FK50L0: RES, 0.05, 1%, 2 W, 2512; Manufacturer: Stackpole Electronics Inc; CompType: Resistor; Value: 0.05; Value_Code: R050; Tolerance_%: 1; Power_W: 2; Value2: 2W; TempCo: 200 ppm/C; EIA_Code: E96; U/M: EA; AEC Category: Q200
R15 R27 = CRCW0603866RFKEA: RES, 866, 1%, 0.1 W, 0603; Manufacturer: Vishay-Dale; CompType: Resistor; Value: 866; Value_Code: 866R; Tolerance_%: 1; Power_W: 0.1; Value2: 0.1W; VDC_V: 75; TempCo: 100 ppm/C; EIA_Code: E96; U/M: EA; AEC Category: Q200; SizeArea_mm2: 1.28; SizeX_mm: 1.6; SizeY_mm: 0.8
R16 R26 = CRCW06038K66FKEA: RES, 8.66 k, 1%, 0.1 W, 0603; Manufacturer: Vishay-Dale; CompType: Resistor; Value: 8.66k; Res_ohm: 8660; Value_Code: 8k66; Tolerance_%: 1; Power_W: 0.1; Value2: 0.1W; VDC_V: 75; TempCo: 100 ppm/C; EIA_Code: E96; U/M: EA; AEC Category: Q200; SizeArea_mm2: 1.28; SizeX_mm: 1.6; SizeY_mm: 0.8
R17 R25 = CRCW060386K6FKEA: RES, 86.6 k, 1%, 0.1 W, 0603; Manufacturer: Vishay-Dale; CompType: Resistor; Value: 86.6k; Res_ohm: 86600; Value_Code: 86k6; Tolerance_%: 1; Power_W: 0.1; Value2: 0.1W; VDC_V: 75; TempCo: 100 ppm/C; EIA_Code: E96; U/M: EA; AEC Category: Q200
R18 R24 = CRCW0603866KFKEA: RES, 866 k, 1%, 0.1 W, 0603; Manufacturer: Vishay-Dale; CompType: Resistor; Value: 866k; Res_ohm: 866000; Tolerance_%: 1; Power_W: 0.1; Value2: 0.1W; VDC_V: 75; TempCo: 100 ppm/C; EIA_Code: E96; U/M: EA; AEC Category: Q200; SizeArea_mm2: 1.28; SizeX_mm: 1.6; SizeY_mm: 0.8
R19 R23 = CRCW060333K0FKEA: RES, 33.0 k, 1%, 0.1 W, 0603; Manufacturer: Vishay-Dale; CompType: Resistor; Value: 33.0k; Res_ohm: 33000; Value_Code: 33k0; Tolerance_%: 1; Power_W: 0.1; Value2: 0.1W; VDC_V: 75; TempCo: 100 ppm/C; U/M: EA; AEC Category: Q200; SizeArea_mm2: 1.28; SizeX_mm: 1.6; SizeY_mm: 0.8
R20 = RC0603FR-071K5L: RES, 1.50 k, 1%, 0.1 W, 0603; Manufacturer: Yageo America; CompType: Resistor; Value: 1.50k; Res_ohm: 1500; Value_Code: 1k50; Tolerance_%: 1; Power_W: 0.1; Value2: 0.1W; VDC_V: 150; TempCo: 200 ppm/C; EIA_Code: E96; U/M: EA; AEC Category: Q200
R21 = CRCW12060000Z0EA: RES, 0, 5%, 0.25 W, 1206; Manufacturer: Vishay-Dale; CompType: Resistor; Value: 0; Value_Code: 0000; Tolerance_%: 5; Power_W: 0.25; Value2: 0.25W; VDC_V: 200; TempCo: 200 ppm/C; EIA_Code: E24; U/M: EA; AEC Category: Q200; SizeArea_mm2: 5.12; SizeX_mm: 3.2; SizeY_mm: 1.6; SizeZ_mm: 1.35
R22 R28 = RC0603FR-072K2L: RES SMD 2.2K OHM 1% 1/10W 0603; Manufacturer: Vishay Dale; CompType: Resistor; Value: 2.20k; Res_ohm: 2200; Value_Code: 2k20; Tolerance_%: 1; Power_W: 0.1; Value2: 0.1W; VDC_V: 150; TempCo: 200 ppm/C; U/M: EA; AEC Category: Q200; SizeArea_mm2: 1.28; SizeX_mm: 1.6; SizeY_mm: 0.8
R29 R30 = CRCW06034K02FKEA: RES, 4.02 k, 1%, 0.1 W, 0603; Manufacturer: Vishay-Dale; CompType: Resistor; Value: 4.02k; Res_ohm: 4020; Value_Code: 4k02; Tolerance_%: 1; Power_W: 0.1; Value2: 0.1W; VDC_V: 75; TempCo: 100 ppm/C; SizeArea_mm2: 1.28; SizeX_mm: 1.6; SizeY_mm: 0.8; EIA_Code: E96; U/M: EA; AEC Category: Q200
TP1-TP19 = 5000: Test Point, Miniature, Red, TH; Manufacturer: Keystone; CompType: Test Point Loop; U/M: EA
U1 U3 = TPS92513HVDGQR: 1.5A Buck LED Driver with Integrated Analog Current Adjust, DGQ0010D; Alternate PartNumber: TPS92513HVDGQT; Manufacturer: Texas Instruments; SymbolCreator: a0411947; SizeArea_mm2: 14.7; SizeAreaWB_mm2: 23.6; SizeX_mm: 4.9; SizeY_mm: 3; SizeZ_mm: 1.1; CompType: IC; U/M: EA
U2 U4 = OPA376AIDBVR: Precision, Low Noise, Low Iq Operational Amplifier, 2.2 to 5.5 V, -40 to 125 degC, 5-pin SOT23 (DBV0005A), Green (RoHS & no Sb/Br); Manufacturer: Texas Instruments; Alternate PartNumber: Equivalent; CMRR(Min)(dB): 76; IIB(Max)(pA): 10; Iq per channel(Max)(mA): 0.95; Number of Channels: 1; Offset Drift(Typ)(uV/C): 0.32; Slew Rate(Typ)(V/us): 2; Sub Family: Low Input Bias Current Amp (<=10pA), Low Noise Amp (<=10nV/rtHz), Low Offset Voltage Amplifier (<=500uV), Low Supply Voltage Amplifier (<=2.7V), Precision Amplifier; Total Supply Voltage(Max)(+5V is 5, +/-5V is 10): 5.5; Total Supply Voltage(Min)(+5V is 5, +/-5V is 10): 2.2; Vio (25C)(Max)(mV): 0.025; Vn at 1kHz(Typ)(nV/rtHz): 7.5

## Sheet TIDA-01096_Hardware.SchDoc: Hardware
size 431 x 279 mm; Date: Not shown in title block; ApprovedBy: Not shown in title block; CheckedBy: Not shown in title block; Author: Not shown in title block; CompanyName: Not shown in title block; DrawnBy: Seetharaman; Engineer: Not shown in title block; Organization: Not shown in title block; Address1: Not shown in title block; Address2: Not shown in title block; Address3: Not shown in title block; Address4: Not shown in title block; DocumentNumber: 1; Revision: Use project parameter SCH_Rev; SheetNumber: 3; SheetTotal: 3; PageSetup: Record=PageOptions¦CenterHorizontal=True¦CenterVertical=True¦PrintScale=1.00¦XCorrection=1.00¦YCorrection=1.00¦PrintKind=0¦BorderSize=5000000¦LeftOffset=0¦BottomOffset=0¦Orientation=2¦PaperLength=1000¦PaperWidth=1000¦Scale=100¦PaperSource=15¦PrintQuality=600¦MediaType=1¦DitherType=10¦PaperKind=Letter¦PrintScaleMode=1
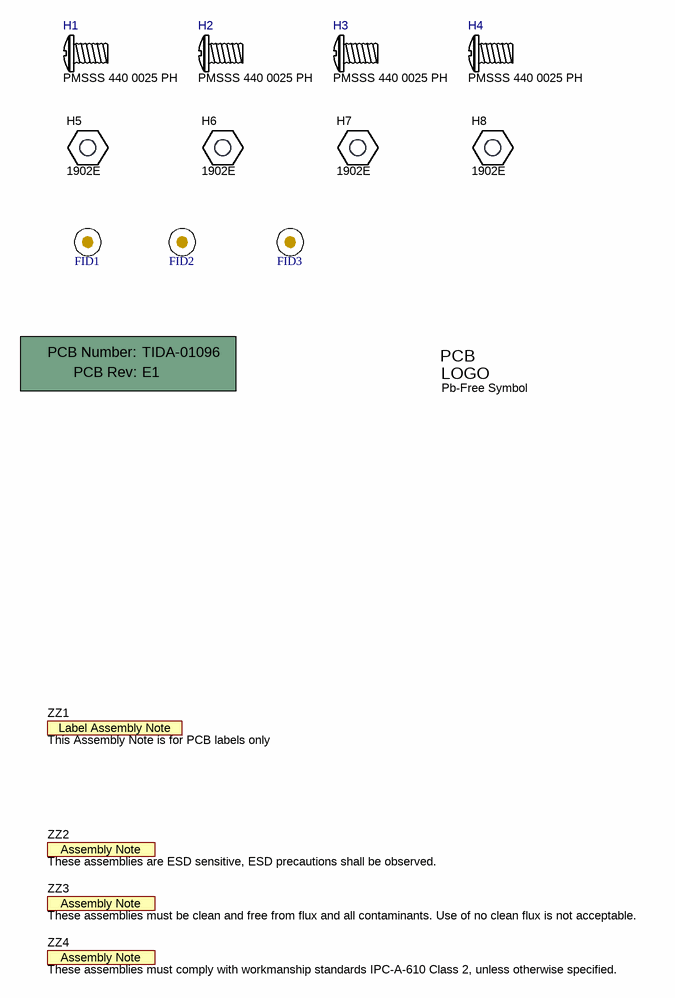
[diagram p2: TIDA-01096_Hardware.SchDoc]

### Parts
!PCB1  Printed Circuit Board  (value not drawn)  (mechanical)
FID1  Fiducial  [Fiducial10-30]  (value not drawn)
FID2  Fiducial  [Fiducial10-30]  (value not drawn)
FID3  Fiducial  [Fiducial10-30]  (value not drawn)
H1  PMSSS 440 0025 PH  [B_F_PMSSS4400025PH]
H2  PMSSS 440 0025 PH  [B_F_PMSSS4400025PH]
H3  PMSSS 440 0025 PH  [B_F_PMSSS4400025PH]
H4  PMSSS 440 0025 PH  [B_F_PMSSS4400025PH]
H5  1902E  [Keystone_1902E]
H6  1902E  [Keystone_1902E]
H7  1902E  [Keystone_1902E]
H8  1902E  [Keystone_1902E]
Logo1  Pb-Free Symbol  [Pb-Free_Overlay_Small]  (no BOM)
ZZ1  This Assembly Note is for PCB labels only  [AssemblyNoteLabel]  (no BOM)
ZZ2  These assemblies are ESD sensitive, ESD precautions shall be observed.  [AssemblyNote]  (no BOM)
ZZ3  These assemblies must be clean and free from flux and all contaminants. Use of no clean flux is not acceptable.  [AssemblyNote]  (no BOM)
ZZ4  These assemblies must comply with workmanship standards IPC-A-610 Class 2, unless otherwise specified.  [AssemblyNote]  (no BOM)

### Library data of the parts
!PCB1 = PCB: Manufacturer: Any; PartNumber: TIDA-01096; SymbolCreator: a0412235
FID1-FID3 = Fiducial: Fiducial mark.  There is nothing to buy or mount.; SymbolCreator: codlsc
H1-H4 = PMSSS 440 0025 PH: MACHINE SCREW PAN PHILLIPS 4-40; Manufacturer: B&F Fastener Supply; CompType: Standoff; SymbolCreator: a0412235
H5-H8 = 1902E: Standoff, Hex, 1"L #4-40 Nylon; Manufacturer: Keystone; CompType: Hardware; SymbolCreator: a0412235
Logo1 = Pb-Free: SymbolCreator: a0412235
ZZ1 = AssemblyNoteLabel: SymbolCreator: a0412235
ZZ2-ZZ4 = AssemblyNote: SymbolCreator: codlsc

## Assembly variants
001: not fitted FID1 FID2 FID3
